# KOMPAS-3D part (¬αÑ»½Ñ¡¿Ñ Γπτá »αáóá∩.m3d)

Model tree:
1. Эскиз:1
2. Операция выдавливания:1
     Расстояние 1 = 2
3. Эскиз:2
4. Операция выдавливания:2
     Расстояние 1 = 6
5. Эскиз:3
6. Операция выдавливания:3
     Расстояние 1 = 2
7. Эскиз:4
8. Операция выдавливания:4
     Расстояние 1 = 6
9. Эскиз:5
10. Операция выдавливания:5
     Расстояние 1 = 1
11. Эскиз:8
12. Вырезать элемент выдавливания:3
     Расстояние 1 = 11
13. Эскиз:9
14. Вырезать элемент выдавливания:4
     Расстояние 1 = 8.39274
15. Эскиз:10
16. Вырезать элемент выдавливания:5
     Расстояние 1 = 11.665
17. Эскиз:11
18. Вырезать элемент выдавливания:6
     Расстояние 1 = 7.28161
19. Зеркальное отражение:1
20. Эскиз:12
21. Операция выдавливания:6
     Расстояние 1 = 2; Расстояние 2 = 2
22. Эскиз:13
23. Операция выдавливания:7
     Расстояние 1 = 6
24. Эскиз:14
25. Операция выдавливания:8
     Расстояние 1 = 1
26. Эскиз:15
27. Вырезать элемент выдавливания:7
     Расстояние 1 = 11.0333
28. Эскиз:16
29. Вырезать элемент выдавливания:8
     Расстояние 1 = 10.0031

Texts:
  крепление туча правая
  Сплав АЛ8  ГОСТ 1583-93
